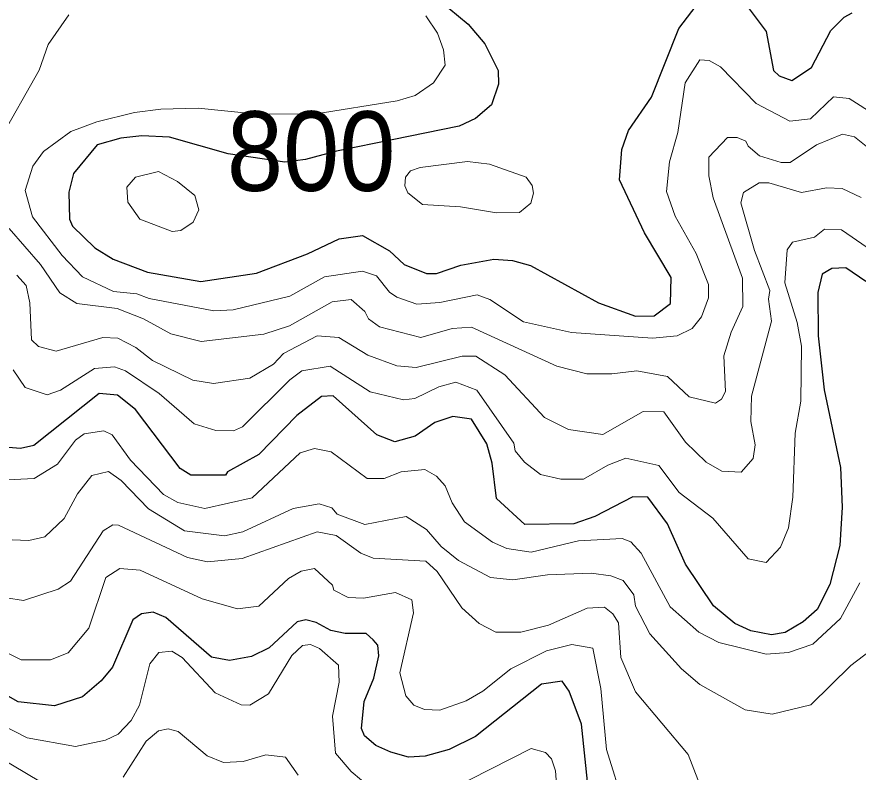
# Model space of a CAD drawing. Extents: x 673.3 to 698.5, y 6984.3 to 7012.3.
# Drawn here: x 681.82 to 682.666, y 6994.352 to 6995.112 of the extents above; entities that cross this region are included whole.
import ezdxf
from ezdxf.enums import TextEntityAlignment as Align

# ---------------------------------------------------------------- set-up
doc = ezdxf.new("R2010")
doc.units = 0
doc.header["$LTSCALE"] = 0.032
doc.layers.add('1', color=7, linetype='Continuous', lineweight=25)
doc.layers.add('2', color=7, linetype='Continuous', lineweight=13)
doc.layers.add('61', color=7, linetype='Continuous')

msp = doc.modelspace()

# ---------------------------------------------------------------- linework, layer by layer
at = {"layer": '1'}
for points in [[(682.2541, 6995.1207), (682.2736, 6995.1044), (682.2902, 6995.0849), (682.3036, 6995.0578), (682.3042, 6995.0442), (682.297, 6995.0233), (682.2809, 6995.0096), (682.2645, 6995.0021), (682.1806, 6994.9849), (682.1413, 6994.9769), (682.1101, 6994.9683), (682.0892, 6994.9658), (682.0321, 6994.9743), (681.9732, 6994.9908), (681.9454, 6994.9924), (681.9243, 6994.9899), (681.9004, 6994.9832), (681.8769, 6994.9545), (681.872, 6994.9356), (681.8726, 6994.9085), (681.8757, 6994.9013), (681.8981, 6994.8798), (681.9165, 6994.8681), (681.951, 6994.8553), (682.0048, 6994.8459), (682.0606, 6994.8542), (682.112, 6994.8737), (682.1439, 6994.8888), (682.1675, 6994.8921), (682.1944, 6994.8766), (682.2091, 6994.8629), (682.2318, 6994.8539), (682.2419, 6994.8539), (682.2663, 6994.8621), (682.2995, 6994.8684), (682.3182, 6994.8668), (682.3361, 6994.862), (682.4048, 6994.8244), (682.4419, 6994.8108), (682.4605, 6994.8112), (682.4769, 6994.8238), (682.4778, 6994.8497), (682.4508, 6994.8948), (682.4257, 6994.9479), (682.428, 6994.9785), (682.4348, 6994.9975), (682.458, 6995.031), (682.4853, 6995.1001), (682.5027, 6995.1231)], [(682.5562, 6995.1199), (682.5731, 6995.0973), (682.5807, 6995.0581), (682.5862, 6995.0526), (682.5989, 6995.0478), (682.6188, 6995.0609), (682.6383, 6995.0981), (682.6518, 6995.1117), (682.6597, 6995.116)], [(682.6733, 6994.8459), (682.6534, 6994.8595), (682.6394, 6994.8587), (682.6295, 6994.8531), (682.6253, 6994.8346), (682.6255, 6994.7912), (682.6317, 6994.7368), (682.648, 6994.6587)], [(682.648, 6994.6587), (682.6496, 6994.619), (682.6472, 6994.5802), (682.6374, 6994.5412), (682.6244, 6994.5161), (682.6103, 6994.5035), (682.5922, 6994.4928), (682.5785, 6994.4907), (682.5579, 6994.4945), (682.5416, 6994.5019), (682.5204, 6994.5197), (682.492, 6994.5617), (682.4741, 6994.6021), (682.4541, 6994.6289), (682.4392, 6994.6292), (682.401, 6994.6094), (682.3798, 6994.6022), (682.3306, 6994.6015), (682.302, 6994.6275), (682.2978, 6994.6633), (682.2922, 6994.6825), (682.2768, 6994.7075), (682.2581, 6994.7101), (682.2401, 6994.704), (682.2204, 6994.6902), (682.2, 6994.6846), (682.1816, 6994.6917), (682.1379, 6994.7308), (682.1262, 6994.7301), (682.1013, 6994.7111), (682.063, 6994.672), (682.0316, 6994.6543), (682.0295, 6994.6511), (681.9948, 6994.6511), (681.9841, 6994.6579), (681.9392, 6994.7172), (681.921, 6994.7314), (681.9026, 6994.7332), (681.8368, 6994.6808), (681.8233, 6994.678), (681.8036, 6994.6797)], [(682.4004, 6994.2792), (682.3875, 6994.4007), (682.375, 6994.4339), (682.368, 6994.4439), (682.3473, 6994.4411), (682.281, 6994.3882), (682.2545, 6994.3753), (682.2302, 6994.3685), (682.2137, 6994.3677), (682.1957, 6994.3727), (682.1809, 6994.3792), (682.1692, 6994.3889), (682.1664, 6994.3964), (682.1689, 6994.4236), (682.1786, 6994.4471), (682.1838, 6994.4694), (682.1828, 6994.4802), (682.1779, 6994.4855), (682.1709, 6994.492), (682.1498, 6994.4918), (682.1355, 6994.4949), (682.1207, 6994.5028), (682.1104, 6994.5057), (682.1016, 6994.5035), (682.0735, 6994.4775), (682.0556, 6994.4686), (682.0336, 6994.4646), (682.0155, 6994.4682), (681.9695, 6994.508), (681.957, 6994.5133), (681.945, 6994.5116), (681.9365, 6994.5055), (681.9158, 6994.4581), (681.9045, 6994.4443), (681.8859, 6994.4281), (681.8575, 6994.419), (681.8212, 6994.4232), (681.7662, 6994.4545)]]:
    msp.add_lwpolyline(points, dxfattribs=at)
at = {"layer": '2'}
for points in [[(681.8722, 6995.1138), (681.8511, 6995.0842), (681.8422, 6995.0584), (681.8013, 6994.9864)], [(682.6836, 6995.0128), (682.6567, 6995.0297), (682.6409, 6995.0313), (682.6178, 6995.0094), (682.597, 6995.007), (682.5633, 6995.0248), (682.5272, 6995.0617), (682.516, 6995.068), (682.5064, 6995.0688), (682.4917, 6995.0457), (682.4843, 6994.9955), (682.4762, 6994.9662), (682.4731, 6994.9364), (682.4816, 6994.9114), (682.5027, 6994.8739), (682.5151, 6994.8427), (682.5152, 6994.8294), (682.5082, 6994.8103), (682.4987, 6994.7984), (682.4836, 6994.7913), (682.4591, 6994.7887), (682.3776, 6994.7945), (682.3292, 6994.8051), (682.2955, 6994.8277), (682.2826, 6994.8325), (682.2452, 6994.8246), (682.2219, 6994.8229), (682.2018, 6994.8299), (682.1944, 6994.8352), (682.1813, 6994.8514), (682.1673, 6994.8562), (682.1292, 6994.8505), (682.0942, 6994.8311), (682.0373, 6994.8172), (682.0177, 6994.8164), (681.9528, 6994.8287), (681.9403, 6994.8334), (681.9171, 6994.8359), (681.8857, 6994.8505), (681.8655, 6994.8718), (681.8354, 6994.9107), (681.828, 6994.9372), (681.836, 6994.9619), (681.8465, 6994.9766), (681.874, 6994.9966), (681.9002, 6995.0063), (681.9382, 6995.0157), (681.9647, 6995.0191), (682.0021, 6995.02), (682.0585, 6995.0143), (682.1188, 6995.0142), (682.2023, 6995.0273), (682.2202, 6995.0327), (682.2386, 6995.0457), (682.2504, 6995.0633), (682.2489, 6995.0786), (682.2429, 6995.0955), (682.231, 6995.1129)], [(681.812, 6994.899), (681.8435, 6994.863), (681.863, 6994.8343), (681.8802, 6994.8238), (681.9207, 6994.8188), (681.9471, 6994.8081), (681.9746, 6994.7933), (682.0052, 6994.7855), (682.068, 6994.7929), (682.094, 6994.8011), (682.1368, 6994.8254), (682.1558, 6994.8277), (682.1698, 6994.8156), (682.1733, 6994.8084), (682.1845, 6994.8002), (682.2259, 6994.7896), (682.2576, 6994.7984), (682.2771, 6994.8), (682.3628, 6994.7606), (682.3929, 6994.7529), (682.4182, 6994.7529), (682.4433, 6994.7561), (682.4739, 6994.7502), (682.4958, 6994.7297), (682.5223, 6994.7236), (682.5283, 6994.7276), (682.5323, 6994.7353), (682.5308, 6994.7711), (682.5379, 6994.7949), (682.5499, 6994.8206), (682.5495, 6994.8492), (682.5198, 6994.9299), (682.5155, 6994.9519), (682.5156, 6994.9708), (682.5344, 6994.9906), (682.5442, 6994.9906), (682.5528, 6994.9868), (682.5552, 6994.9818), (682.5664, 6994.9721), (682.5882, 6994.9654), (682.5972, 6994.9654), (682.6239, 6994.9831), (682.6501, 6994.994), (682.6619, 6994.9912), (682.6888, 6994.9699)], [(681.8293, 6994.8418), (681.8329, 6994.8242), (681.8345, 6994.7873), (681.8415, 6994.7804), (681.8594, 6994.7757), (681.9062, 6994.7894), (681.9214, 6994.7889), (681.9394, 6994.7795), (681.9563, 6994.7664), (681.9966, 6994.7466), (682.0174, 6994.7431), (682.054, 6994.7487), (682.0779, 6994.7626), (682.088, 6994.7734), (682.1218, 6994.7912), (682.1435, 6994.7896), (682.1726, 6994.7718), (682.2019, 6994.7609), (682.2212, 6994.7594), (682.2674, 6994.7707), (682.2812, 6994.7707), (682.3103, 6994.7518), (682.3505, 6994.7091), (682.3746, 6994.6969), (682.4091, 6994.6918), (682.4495, 6994.7151), (682.4704, 6994.7147), (682.4921, 6994.6841), (682.5128, 6994.6643), (682.5286, 6994.6551), (682.548, 6994.654), (682.5601, 6994.6679), (682.5623, 6994.6816), (682.5577, 6994.705), (682.5585, 6994.7306), (682.5787, 6994.806), (682.5756, 6994.8279), (682.577, 6994.8367), (682.5616, 6994.8769), (682.5479, 6994.9249), (682.5503, 6994.9353), (682.5661, 6994.945), (682.5758, 6994.945), (682.6087, 6994.9353), (682.6338, 6994.9401), (682.6498, 6994.9394), (682.6686, 6994.9303)], [(682.6748, 6994.8801), (682.6491, 6994.8976), (682.6318, 6994.8985), (682.6219, 6994.8904), (682.5998, 6994.8854), (682.5945, 6994.8776), (682.5919, 6994.8444), (682.6045, 6994.8045), (682.6089, 6994.7809), (682.6082, 6994.7254), (682.6024, 6994.6933), (682.5999, 6994.6288), (682.5958, 6994.5982), (682.5877, 6994.5787), (682.5734, 6994.5631), (682.5552, 6994.567), (682.5195, 6994.6077), (682.4857, 6994.6335), (682.4654, 6994.6609), (682.4322, 6994.668), (682.4141, 6994.6611), (682.3896, 6994.647), (682.3667, 6994.647), (682.3464, 6994.6519), (682.3302, 6994.6643), (682.3209, 6994.6755), (682.3195, 6994.6831), (682.2823, 6994.7364), (682.2613, 6994.7447)], [(681.8196, 6994.8523), (681.8293, 6994.8418)], [(682.2613, 6994.7447), (682.2441, 6994.7398), (682.2199, 6994.728), (682.2087, 6994.7268), (682.1751, 6994.7348), (682.1347, 6994.7607), (682.1065, 6994.756), (682.0944, 6994.747), (682.0467, 6994.6998), (682.0375, 6994.6958), (682.0198, 6994.6959), (681.998, 6994.7028), (681.9628, 6994.7332), (681.9289, 6994.7561), (681.9178, 6994.76), (681.898, 6994.7584), (681.8637, 6994.7366), (681.8503, 6994.7318), (681.828, 6994.7392), (681.816, 6994.7571)], [(681.8038, 6994.6461), (681.8371, 6994.6476), (681.8608, 6994.662), (681.8788, 6994.6864), (681.8873, 6994.6927), (681.9074, 6994.6958), (681.9157, 6994.6916), (681.934, 6994.6663), (681.9672, 6994.6317), (681.9817, 6994.6237), (682.0087, 6994.6177), (682.0565, 6994.6283), (682.1047, 6994.6736), (682.1192, 6994.6778), (682.1359, 6994.6745), (682.1719, 6994.6477), (682.1891, 6994.6477), (682.2061, 6994.6544), (682.2299, 6994.6567), (682.2416, 6994.6502), (682.2505, 6994.6403), (682.2576, 6994.6231), (682.2698, 6994.6042), (682.298, 6994.5837), (682.3126, 6994.5775), (682.3371, 6994.5737), (682.3846, 6994.585), (682.4286, 6994.5875), (682.4371, 6994.584), (682.4475, 6994.5727), (682.4766, 6994.5186), (682.5054, 6994.4933), (682.5255, 6994.4827), (682.5732, 6994.4711), (682.5956, 6994.4727), (682.62, 6994.4812), (682.6481, 6994.507), (682.6675, 6994.5427)], [(681.815, 6994.5861), (681.8317, 6994.5854), (681.848, 6994.5891), (681.8674, 6994.6074), (681.8809, 6994.6323), (681.8953, 6994.6508), (681.912, 6994.6549), (681.9245, 6994.6457), (681.9521, 6994.6173), (681.9883, 6994.5952), (682.0287, 6994.59), (682.0469, 6994.5942), (682.0977, 6994.6175), (682.1239, 6994.6224), (682.1365, 6994.6182), (682.1417, 6994.6119), (682.1696, 6994.6014), (682.2111, 6994.6094), (682.2316, 6994.5966), (682.2465, 6994.5795), (682.2638, 6994.5652), (682.2962, 6994.5482), (682.3185, 6994.546), (682.3534, 6994.5508), (682.3972, 6994.5526), (682.4172, 6994.55), (682.4295, 6994.5453), (682.4402, 6994.5307), (682.442, 6994.5194), (682.4562, 6994.4917), (682.4881, 6994.4565), (682.5066, 6994.4407), (682.5521, 6994.4151), (682.5794, 6994.4109), (682.6182, 6994.4202), (682.6585, 6994.4597), (682.6966, 6994.4887)], [(682.2673, 6994.5178), (682.2424, 6994.5541), (682.2311, 6994.5645), (682.1781, 6994.5675), (682.1658, 6994.5726), (682.1408, 6994.5905), (682.1217, 6994.594), (682.0465, 6994.5672), (682.0114, 6994.564), (681.9914, 6994.5683), (681.9219, 6994.6008), (681.9162, 6994.6013), (681.9066, 6994.5951), (681.8736, 6994.5445), (681.8612, 6994.5366), (681.8266, 6994.5249), (681.8094, 6994.5277)], [(682.4304, 6994.3183), (682.4126, 6994.3754), (682.407, 6994.4366), (682.3988, 6994.4771), (682.3778, 6994.4808), (682.3524, 6994.4743), (682.3166, 6994.4564), (682.2883, 6994.4338), (682.2717, 6994.4242), (682.2452, 6994.4149), (682.2296, 6994.4155), (682.219, 6994.4199), (682.211, 6994.4291), (682.205, 6994.4525), (682.2187, 6994.5128), (682.2171, 6994.5256), (682.2004, 6994.533), (682.1683, 6994.5273), (682.1529, 6994.5281), (682.1384, 6994.5354), (682.1371, 6994.5404), (682.1192, 6994.5572), (682.1056, 6994.5544), (682.0929, 6994.5472), (682.063, 6994.5192), (682.0417, 6994.5166), (682.006, 6994.5268), (681.9438, 6994.5556), (681.9234, 6994.5573), (681.9094, 6994.5483), (681.8923, 6994.4974), (681.8713, 6994.4723), (681.8537, 6994.4653), (681.8241, 6994.4654), (681.7951, 6994.4797)], [(682.5217, 6994.3008), (682.4948, 6994.3701), (682.4419, 6994.4331), (682.4272, 6994.4678), (682.4249, 6994.5027), (682.4191, 6994.5117), (682.4106, 6994.5183), (682.3931, 6994.5174), (682.3545, 6994.5003), (682.3266, 6994.4931), (682.3013, 6994.4932), (682.2848, 6994.5021), (682.2673, 6994.5178)], [(681.781, 6994.412), (681.8302, 6994.387), (681.8789, 6994.3783), (681.9089, 6994.3847), (681.9215, 6994.3907), (681.9348, 6994.4045), (681.9431, 6994.4197), (681.9534, 6994.4613), (681.9624, 6994.4729), (681.9755, 6994.4741), (681.9859, 6994.4678), (682.0191, 6994.4321), (682.0453, 6994.4201), (682.0542, 6994.4198), (682.0729, 6994.4311), (682.0962, 6994.4697), (682.1071, 6994.4798), (682.1149, 6994.4807), (682.1241, 6994.4768), (682.1431, 6994.4599), (682.1438, 6994.4431), (682.1373, 6994.4087), (682.1403, 6994.3716), (682.1559, 6994.3532), (682.1768, 6994.3358)], [(682.1028, 6994.3495), (682.0898, 6994.3677), (682.0701, 6994.37), (682.0473, 6994.3632), (682.0276, 6994.3621), (682.0112, 6994.369), (681.982, 6994.3935), (681.9719, 6994.396), (681.9621, 6994.394), (681.9498, 6994.3837), (681.9266, 6994.3476)], [(681.8434, 6994.3428), (681.7711, 6994.3855)], [(682.2553, 6994.3348), (682.3368, 6994.3764), (682.3515, 6994.3722), (682.3573, 6994.3659), (682.3613, 6994.3538), (682.3645, 6994.3134)]]:
    msp.add_lwpolyline(points, dxfattribs=at)
for points in [[(682.3022, 6994.9148), (682.3252, 6994.915), (682.3367, 6994.9246), (682.3392, 6994.9347), (682.3378, 6994.9423), (682.332, 6994.9507), (682.2951, 6994.9638), (682.273, 6994.9663), (682.2254, 6994.9605), (682.2156, 6994.957), (682.2107, 6994.9508), (682.2099, 6994.9419), (682.2128, 6994.9351), (682.2276, 6994.9231), (682.2658, 6994.9207)], [(681.9759, 6994.8962), (681.9845, 6994.897), (681.9969, 6994.9055), (682.0029, 6994.9177), (681.9987, 6994.9324), (681.9813, 6994.9465), (681.9622, 6994.9563), (681.939, 6994.9508), (681.9305, 6994.9406), (681.9314, 6994.9256), (681.9436, 6994.9085)]]:
    msp.add_lwpolyline(points, close=True, dxfattribs=at)

# ---------------------------------------------------------------- texts
at = {"layer": '61', "width": 0.95}
msp.add_text('800', height=0.08, dxfattribs=at).set_placement((682.1157, 6994.9369), align=Align.CENTER)

doc.saveas('drawing.dxf')
